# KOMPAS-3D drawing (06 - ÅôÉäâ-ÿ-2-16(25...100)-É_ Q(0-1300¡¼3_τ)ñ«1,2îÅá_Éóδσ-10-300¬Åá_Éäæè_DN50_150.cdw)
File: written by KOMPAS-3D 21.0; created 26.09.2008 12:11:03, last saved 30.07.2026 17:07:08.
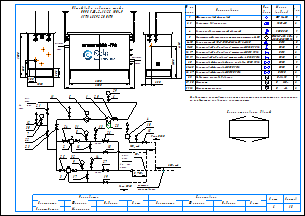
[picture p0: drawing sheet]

Sheets 1-2: A3, landscape

Document properties: Наименование: Макро:21; Автор: RaskoAdmin; Форматы листов документа: 2xA3; Полное имя файла: \\ur38nt01\Departments\КТО\КБ ПУРДГ\Заявки\Прайс-лист на типовые шкафы ГРПШ\ПУРДГ_стандарт_30_04_2026\ПУРДГ с РДСК\ПУРДГ-Ш-2-16(25...100)-Р_ Q(0-1300нм3_ч)до1,2МПа_Рвых-10-300кПа_РДСК_DN50_150.cdw

Title block, sheet 1: Наименование: Пункт учета газа / ПУГ-Ш-400-Р / ЛГТИ.485922.001ТУ; designation: ЛГТИ.03.4411141; sheet number: 1; Количество листов документа: 2; organisation: ООО "ЭЛЬСТЕР Газэлектроника"; Форматы листов документа: A3; stored path: C:\Рабочие документы\Компас\ПУГ\Схема.cdw; Разработал: Устинов; Проверил: Кошкин; Утвердил: Кошкин
Title block, sheet 2: sheet number: 2; stored path: D:\Рабочие документы\Заявки\ПУРДГ\ПУРДГ-ШУЭО-2-100-Р 4411220.cdw; designation, second copy: ЛГТИ.03.4411141-

Views: Вид 1, Вид 2
Referenced files: wcvoit.frw
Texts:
  Normal
  № на
  схеме
  Усл.
  обозн.
  Марка
  (модель)
  Кол.
  Фильтр газовый фланцевый
  ФГ 16-50
  Регулятор давления газа
  РДСК-50
  Клапан предохранительный сбросной
  КПС DN20
  Измерительный комплекс с ротационным счетчиком Ду50
  СГ-ЭК-Р-(0,2...2,0)-
  Кран кнопочный VE-РАСКО-НЗ-1,6-G1/2-М20
  DN15
  Кран шаровой "под приварку" штуцерный DN20 PN16
  DN20
  Кран шаровой "под приварку" штуцерный DN15 PN16
  Кран шаровой "под приварку" штуцерный п/п DN20 PN16
  Кран шаровой фланцевый с мех. приводом DN50 PN16
  Кран шаровой фланцевый DN50 PN16
  Кран шаровой фланцевый DN150 PN16
  DN50
  DN150
  Индикатор перепада давления
  Манометр
  Манометр-напоромер
  Delta 15
  0...     МПа
  0...     кПа
  Общий вид и габариты шкафа
  ПУРДГ-Ш-2-16(25...100)-Р
  Выход газа
  Вход газа
  logo-rasko-ge.png
  DN 1
  местное
  сопротивление
  Римп DN20
  Выход
  газа
  Р=     кПа
  Вход
  Р=       МПа
  PDI
  Схема открывания дверей
  Предприятие изготовитель может заменять комплектующие на аналогичные,
  не ухудшающие заявленных характеристик.
  Должность
  Конструктор
  Фамилия
  Подпись
  Дата
  Согласовано
  Максимкин
  Лист
  Листов
  POLYLINE_STYLE_0.18_RGB_0_0_0
  POLYLINE_STYLE_0.50_RGB_0_0_0
  POLYLINE_STYLE_0.34_RGB_0_0_0
  PHANTOM_RGB_0_0_0_SC_1_THICK_0.18
  K5LT_THIN_RGB_0_0_0_THICK_0.18
  K5LT32769_RGB_0_0_0_THICK_0.18
  K5LT12_RGB_0_0_0_SC_1_THICK_0.18
  K5LT_DASHED_RGB_0_0_0_SC_1_THICK_0.18
  ACISOTGL_RGB_0_0_0_SC_0.8_THICK_0.25
  CONTINUOUS_RGB_0_127_31_THICK_0.3
  CONTINUOUS_RGB_0_0_255_THICK_0.35
  CONTINUOUS_RGB_255_0_0_THICK_0.35
  POLYLINE_STYLE_0.25_RGB_0_0_0
  CONTINUOUS_RGB_0_0_0_THICK_0.5
  POLYLINE_STYLE_0.35_RGB_0_0_255
  CONTINUOUS_RGB_0_0_0_THICK_0.4
  CONTINUOUS_RGB_0_0_0_THICK_0.35
  НЕВИДИМАЯ_RGB_0_0_0_SC_0.3_THICK_0.25
  СONTINUOUS_RGB_0_0_0_THICK_0.25
  ОСЕВАЯ2_RGB_248_153_30_SC_0.3_THICK_0.25
  Без оформления
Dimensions and other numbers on the sheet: 1; 2, 3; 2; 4; 5; 6-10; 11-15; 16, 17; 18, 19; 20; 21-25; 26, 27; 28; 29, 30; 31, 32; 1500; 250; 300; 1050; 550; 305; 2500; 4130; 2000; 2800; 5,,,7DN 1; 7; 30; 12; 21; 22; 23; 11; 6; 29; 24; 31; 8; 16; 13; 26; 18; 10; 15; 25; 32; 9; 3; 17; 14; 27; 19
